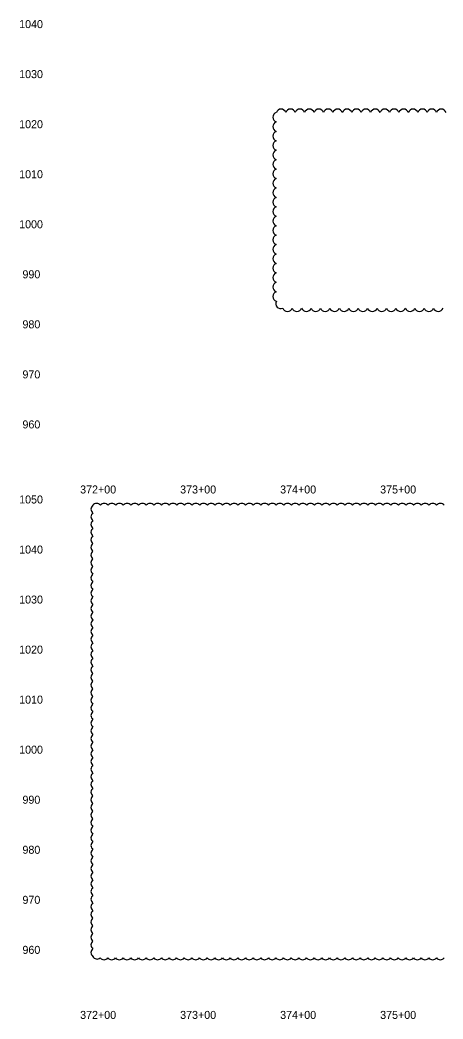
# Model space of a CAD drawing. Extents: x 1617657 to 1619318, y 1076167 to 1077194.
# Drawn here: x 1617657 to 1618080, y 1076167 to 1077165 of the extents above; entities that cross this region are included whole.
import ezdxf

# ---------------------------------------------------------------- set-up
doc = ezdxf.new("R2010")
doc.units = 0
doc.layers.add('Default', color=7, linetype='Continuous')
doc.layers.add('RD_SHT_TX', color=7, linetype='Continuous')

msp = doc.modelspace()

# ---------------------------------------------------------------- linework, layer by layer
at = {"layer": 'RD_SHT_TX'}
for centre, radius, start, end in [((1617918.51, 1077071.48), 4.94, 17.5, 162.5), ((1617927.93, 1077071.48), 4.94, 17.5, 162.5), ((1617937.36, 1077071.48), 4.94, 17.5, 162.5), ((1617946.79, 1077071.48), 4.94, 17.5, 162.5), ((1617956.21, 1077071.48), 4.94, 17.5, 162.5), ((1617965.64, 1077071.48), 4.94, 17.5, 162.5), ((1617975.07, 1077071.48), 4.94, 17.5, 162.5), ((1617984.49, 1077071.48), 4.94, 17.5, 162.5), ((1617993.92, 1077071.48), 4.94, 17.5, 162.5), ((1618003.35, 1077071.48), 4.94, 17.5, 162.5), ((1618012.77, 1077071.48), 4.94, 17.5, 162.5), ((1618022.2, 1077071.48), 4.94, 17.5, 162.5), ((1618031.63, 1077071.48), 4.94, 17.5, 162.5), ((1618041.05, 1077071.48), 4.94, 17.5, 162.5), ((1618050.48, 1077071.48), 4.94, 17.5, 162.5), ((1618059.91, 1077071.48), 4.94, 17.5, 162.5), ((1618069.33, 1077071.48), 4.94, 17.5, 162.5), ((1618078.76, 1077071.48), 4.94, 17.5, 162.5), ((1617915.28, 1077068.26), 4.94, 107.5, 252.5), ((1617915.28, 1077058.83), 4.94, 107.5, 252.5), ((1617915.28, 1077049.4), 4.94, 107.5, 252.5), ((1617915.28, 1077039.98), 4.94, 107.5, 252.5), ((1617915.28, 1077030.55), 4.94, 107.5, 252.5), ((1617915.28, 1077021.12), 4.94, 107.5, 252.5), ((1617915.28, 1077011.7), 4.94, 107.5, 252.5), ((1617915.28, 1077002.27), 4.94, 107.5, 252.5), ((1617915.28, 1076992.84), 4.94, 107.5, 252.5), ((1617915.28, 1076983.42), 4.94, 107.5, 252.5), ((1617915.28, 1076973.99), 4.94, 107.5, 252.5), ((1617915.28, 1076964.56), 4.94, 107.5, 252.5), ((1617915.28, 1076955.14), 4.94, 107.5, 252.5), ((1617915.28, 1076945.71), 4.94, 107.5, 252.5), ((1617915.28, 1076936.28), 4.94, 107.5, 252.5), ((1617915.28, 1076926.86), 4.94, 107.5, 252.5), ((1617915.28, 1076917.43), 4.94, 107.5, 252.5), ((1617915.28, 1076908), 4.94, 107.5, 252.5), ((1617915.28, 1076898.58), 4.94, 107.5, 252.5), ((1617915.28, 1076889.15), 4.94, 107.5, 252.5), ((1617918.1, 1076882.01), 4.94, 150.59394, 295.59394), ((1617924.95, 1076879.04), 4.94, 197.5, 342.5), ((1617934.37, 1076879.04), 4.94, 197.5, 342.5), ((1617943.8, 1076879.04), 4.94, 197.5, 342.5), ((1617953.23, 1076879.04), 4.94, 197.5, 342.5), ((1617962.65, 1076879.04), 4.94, 197.5, 342.5), ((1617972.08, 1076879.04), 4.94, 197.5, 342.5), ((1617981.51, 1076879.04), 4.94, 197.5, 342.5), ((1617990.93, 1076879.04), 4.94, 197.5, 342.5), ((1618000.36, 1076879.04), 4.94, 197.5, 342.5), ((1618009.79, 1076879.04), 4.94, 197.5, 342.5), ((1618019.21, 1076879.04), 4.94, 197.5, 342.5), ((1618028.64, 1076879.04), 4.94, 197.5, 342.5), ((1618038.07, 1076879.04), 4.94, 197.5, 342.5), ((1618047.49, 1076879.04), 4.94, 197.5, 342.5), ((1618056.92, 1076879.04), 4.94, 197.5, 342.5), ((1618066.35, 1076879.04), 4.94, 197.5, 342.5), ((1618075.77, 1076879.04), 4.94, 197.5, 342.5), ((1617733.45, 1076676.68), 4.99, 130, 230), ((1617734.06, 1076677.29), 4.99, 40, 140), ((1617741.7, 1076677.29), 4.99, 40, 140), ((1617749.34, 1076677.29), 4.99, 40, 140), ((1617756.98, 1076677.29), 4.99, 40, 140), ((1617764.62, 1076677.29), 4.99, 40, 140), ((1617772.26, 1076677.29), 4.99, 40, 140), ((1617779.9, 1076677.29), 4.99, 40, 140), ((1617787.54, 1076677.29), 4.99, 40, 140), ((1617795.18, 1076677.29), 4.99, 40, 140), ((1617802.82, 1076677.29), 4.99, 40, 140), ((1617810.46, 1076677.29), 4.99, 40, 140), ((1617818.1, 1076677.29), 4.99, 40, 140), ((1617825.74, 1076677.29), 4.99, 40, 140), ((1617833.38, 1076677.29), 4.99, 40, 140), ((1617841.02, 1076677.29), 4.99, 40, 140), ((1617848.66, 1076677.29), 4.99, 40, 140), ((1617856.3, 1076677.29), 4.99, 40, 140), ((1617863.94, 1076677.29), 4.99, 40, 140), ((1617871.58, 1076677.29), 4.99, 40, 140), ((1617879.22, 1076677.29), 4.99, 40, 140), ((1617886.86, 1076677.29), 4.99, 40, 140), ((1617894.5, 1076677.29), 4.99, 40, 140), ((1617902.14, 1076677.29), 4.99, 40, 140), ((1617909.78, 1076677.29), 4.99, 40, 140), ((1617917.42, 1076677.29), 4.99, 40, 140), ((1617925.06, 1076677.29), 4.99, 40, 140), ((1617932.7, 1076677.29), 4.99, 40, 140), ((1617940.34, 1076677.29), 4.99, 40, 140), ((1617947.98, 1076677.29), 4.99, 40, 140), ((1617955.62, 1076677.29), 4.99, 40, 140), ((1617963.26, 1076677.29), 4.99, 40, 140), ((1617970.9, 1076677.29), 4.99, 40, 140), ((1617978.54, 1076677.29), 4.99, 40, 140), ((1617986.18, 1076677.29), 4.99, 40, 140), ((1617993.82, 1076677.29), 4.99, 40, 140), ((1618001.46, 1076677.29), 4.99, 40, 140), ((1618009.1, 1076677.29), 4.99, 40, 140), ((1618016.74, 1076677.29), 4.99, 40, 140), ((1618024.38, 1076677.29), 4.99, 40, 140), ((1618032.02, 1076677.29), 4.99, 40, 140), ((1618039.66, 1076677.29), 4.99, 40, 140), ((1618047.3, 1076677.29), 4.99, 40, 140), ((1618054.94, 1076677.29), 4.99, 40, 140), ((1618062.58, 1076677.29), 4.99, 40, 140), ((1618070.22, 1076677.29), 4.99, 40, 140), ((1618077.86, 1076677.29), 4.99, 40, 140), ((1617733.45, 1076669.04), 4.99, 130, 230), ((1617733.45, 1076661.4), 4.99, 130, 230), ((1617733.45, 1076653.76), 4.99, 130, 230), ((1617733.45, 1076646.12), 4.99, 130, 230), ((1617733.45, 1076638.48), 4.99, 130, 230), ((1617733.45, 1076630.84), 4.99, 130, 230), ((1617733.45, 1076623.2), 4.99, 130, 230), ((1617733.45, 1076615.56), 4.99, 130, 230), ((1617733.45, 1076607.92), 4.99, 130, 230), ((1617733.45, 1076600.28), 4.99, 130, 230), ((1617733.45, 1076592.63), 4.99, 130, 230), ((1617733.45, 1076584.99), 4.99, 130, 230), ((1617733.45, 1076577.35), 4.99, 130, 230), ((1617733.45, 1076569.71), 4.99, 130, 230), ((1617733.45, 1076562.07), 4.99, 130, 230), ((1617733.45, 1076554.43), 4.99, 130, 230), ((1617733.45, 1076546.79), 4.99, 130, 230), ((1617733.45, 1076539.15), 4.99, 130, 230), ((1617733.45, 1076531.51), 4.99, 130, 230), ((1617733.45, 1076523.87), 4.99, 130, 230), ((1617733.45, 1076516.23), 4.99, 130, 230), ((1617733.45, 1076508.59), 4.99, 130, 230), ((1617733.45, 1076500.95), 4.99, 130, 230), ((1617733.45, 1076493.31), 4.99, 130, 230), ((1617733.45, 1076485.67), 4.99, 130, 230), ((1617733.45, 1076478.03), 4.99, 130, 230), ((1617733.45, 1076470.39), 4.99, 130, 230), ((1617733.45, 1076462.75), 4.99, 130, 230), ((1617733.45, 1076455.11), 4.99, 130, 230), ((1617733.45, 1076447.47), 4.99, 130, 230), ((1617733.45, 1076439.83), 4.99, 130, 230), ((1617733.45, 1076432.19), 4.99, 130, 230), ((1617733.45, 1076424.55), 4.99, 130, 230), ((1617733.45, 1076416.91), 4.99, 130, 230), ((1617733.45, 1076409.27), 4.99, 130, 230), ((1617733.45, 1076401.63), 4.99, 130, 230), ((1617733.45, 1076393.99), 4.99, 130, 230), ((1617733.45, 1076386.35), 4.99, 130, 230), ((1617733.45, 1076378.71), 4.99, 130, 230), ((1617733.45, 1076371.07), 4.99, 130, 230), ((1617733.45, 1076363.43), 4.99, 130, 230), ((1617733.45, 1076355.79), 4.99, 130, 230), ((1617733.45, 1076348.15), 4.99, 130, 230), ((1617733.45, 1076340.51), 4.99, 130, 230), ((1617733.45, 1076332.87), 4.99, 130, 230), ((1617733.45, 1076325.23), 4.99, 130, 230), ((1617733.45, 1076317.59), 4.99, 130, 230), ((1617733.45, 1076309.95), 4.99, 130, 230), ((1617733.45, 1076302.31), 4.99, 130, 230), ((1617733.45, 1076294.67), 4.99, 130, 230), ((1617733.45, 1076287.03), 4.99, 130, 230), ((1617733.45, 1076279.39), 4.99, 130, 230), ((1617733.45, 1076271.75), 4.99, 130, 230), ((1617733.45, 1076264.11), 4.99, 130, 230), ((1617733.45, 1076256.47), 4.99, 130, 230), ((1617733.45, 1076248.83), 4.99, 130, 230), ((1617733.45, 1076241.19), 4.99, 130, 230), ((1617733.44, 1076233.55), 4.99, 130, 230), ((1617734.64, 1076232.09), 4.99, 208.20061, 308.20061), ((1617741.54, 1076231.38), 4.99, 220, 320), ((1617749.18, 1076231.38), 4.99, 220, 320), ((1617756.83, 1076231.38), 4.99, 220, 320), ((1617764.47, 1076231.38), 4.99, 220, 320), ((1617772.11, 1076231.38), 4.99, 220, 320), ((1617779.75, 1076231.38), 4.99, 220, 320), ((1617787.39, 1076231.38), 4.99, 220, 320), ((1617795.03, 1076231.38), 4.99, 220, 320), ((1617802.67, 1076231.38), 4.99, 220, 320), ((1617810.31, 1076231.38), 4.99, 220, 320), ((1617817.95, 1076231.38), 4.99, 220, 320), ((1617825.59, 1076231.38), 4.99, 220, 320), ((1617833.23, 1076231.38), 4.99, 220, 320), ((1617840.87, 1076231.38), 4.99, 220, 320), ((1617848.51, 1076231.38), 4.99, 220, 320), ((1617856.15, 1076231.38), 4.99, 220, 320), ((1617863.79, 1076231.38), 4.99, 220, 320), ((1617871.43, 1076231.38), 4.99, 220, 320), ((1617879.07, 1076231.38), 4.99, 220, 320), ((1617886.71, 1076231.38), 4.99, 220, 320), ((1617894.35, 1076231.38), 4.99, 220, 320), ((1617901.99, 1076231.38), 4.99, 220, 320), ((1617909.63, 1076231.38), 4.99, 220, 320), ((1617917.27, 1076231.38), 4.99, 220, 320), ((1617924.91, 1076231.38), 4.99, 220, 320), ((1617932.55, 1076231.38), 4.99, 220, 320), ((1617940.19, 1076231.38), 4.99, 220, 320), ((1617947.83, 1076231.38), 4.99, 220, 320), ((1617955.47, 1076231.38), 4.99, 220, 320), ((1617963.11, 1076231.38), 4.99, 220, 320), ((1617970.75, 1076231.38), 4.99, 220, 320), ((1617978.39, 1076231.38), 4.99, 220, 320), ((1617986.03, 1076231.38), 4.99, 220, 320), ((1617993.67, 1076231.38), 4.99, 220, 320), ((1618001.31, 1076231.38), 4.99, 220, 320), ((1618008.95, 1076231.38), 4.99, 220, 320), ((1618016.59, 1076231.38), 4.99, 220, 320), ((1618024.23, 1076231.38), 4.99, 220, 320), ((1618031.87, 1076231.38), 4.99, 220, 320), ((1618039.51, 1076231.38), 4.99, 220, 320), ((1618047.15, 1076231.38), 4.99, 220, 320), ((1618054.79, 1076231.38), 4.99, 220, 320), ((1618062.43, 1076231.38), 4.99, 220, 320), ((1618070.07, 1076231.38), 4.99, 220, 320), ((1618077.71, 1076231.38), 4.99, 220, 320)]:
    msp.add_arc(centre, radius, start, end, dxfattribs=at)

# ---------------------------------------------------------------- texts
at = {"layer": 'Default'}
for s, p in [('1040', (1617656.63, 1077157.31)), ('1030', (1617656.63, 1077107.31)), ('1020', (1617656.63, 1077057.31)), ('1010', (1617656.63, 1077007.31)), ('1000', (1617656.63, 1076957.31)), ('990', (1617659.94, 1076907.31)), ('980', (1617659.94, 1076857.31)), ('970', (1617659.94, 1076807.31)), ('960', (1617659.94, 1076757.31)), ('372+00', (1617717.62, 1076692.31)), ('373+00', (1617817.62, 1076692.31)), ('374+00', (1617917.62, 1076692.31)), ('375+00', (1618017.62, 1076692.31)), ('1050', (1617656.63, 1076682.31)), ('1040', (1617656.63, 1076632.31)), ('1030', (1617656.63, 1076582.31)), ('1020', (1617656.63, 1076532.31)), ('1010', (1617656.63, 1076482.31)), ('1000', (1617656.63, 1076432.31)), ('990', (1617659.94, 1076382.31)), ('980', (1617659.94, 1076332.31)), ('970', (1617659.94, 1076282.31)), ('960', (1617659.94, 1076232.31)), ('372+00', (1617717.62, 1076167.31)), ('373+00', (1617817.62, 1076167.31)), ('374+00', (1617917.62, 1076167.31)), ('375+00', (1618017.62, 1076167.31))]:
    msp.add_text(s, height=8, dxfattribs=at).set_placement(p)

doc.saveas('drawing.dxf')
